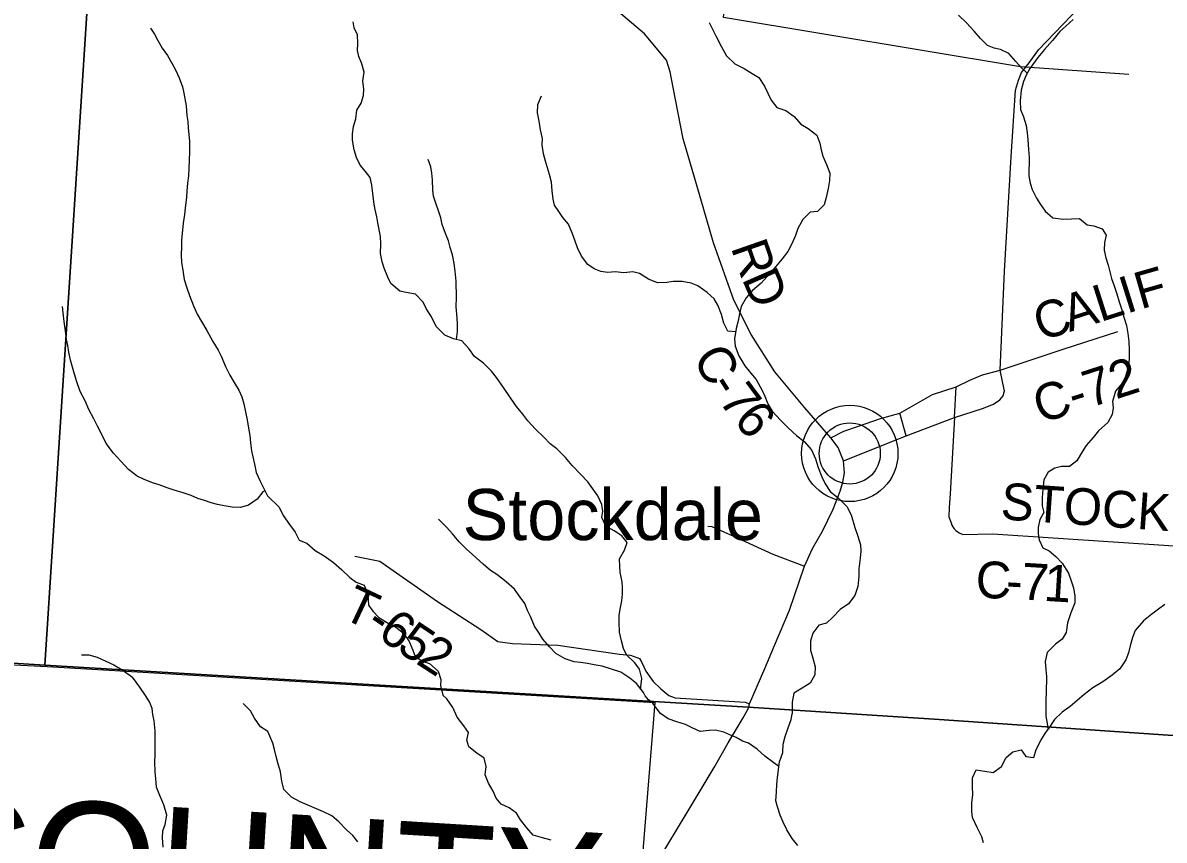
# Model space of a CAD drawing. Extents: x 0 to 40.8, y 0 to 22.
# Drawn here: x 3.414 to 5.177, y 17.063 to 18.326 of the extents above; entities that cross this region are included whole.
import ezdxf

# ---------------------------------------------------------------- set-up
doc = ezdxf.new("R2010")
doc.units = 0
for name, color, linetype in [('Default', 7, 'Continuous'), ('GM_X_County_Road', 7, 'Continuous'), ('GM_X_County_Road_Text', 7, 'Continuous'), ('GM_X_County_Text', 7, 'Continuous'), ('GM_X_Minor_River', 7, 'Continuous'), ('GM_X_Section', 7, 'Continuous'), ('GM_X_State_Route', 7, 'Continuous'), ('GM_X_Township_Road', 7, 'Continuous'), ('GM_X_Township_Road_Text', 7, 'Continuous'), ('GM_X_Unincorporated', 7, 'Continuous'), ('GM_X_Unincorporated_Location', 7, 'Continuous'), ('GM_X_Unincorporated_Text', 7, 'Continuous'), ('SH_Cut_Line', 7, 'Continuous')]:
    doc.layers.add(name, color=color, linetype=linetype)

msp = doc.modelspace()

# ---------------------------------------------------------------- linework, layer by layer
at = {"layer": 'Default'}
for points in [[(3.6829, 20.9), (2.1, 20.9), (2.1, 17.4153), (2.4594, 17.3966), (2.8463, 17.3693), (2.8484, 17.3691), (3.1244, 17.3534), (3.4481, 17.3334), (3.5638, 19.132), (3.5742, 19.2945), (3.575, 19.3064), (3.6386, 20.2396), (3.6672, 20.5588), (3.6703, 20.6733)], [(2.1, 16.4387), (2.1, 14.1), (8.9, 14.1), (8.9, 16.9831), (7.7161, 17.0658), (7.7144, 17.066), (7.54, 17.0745), (7.4495, 17.0841), (6.9172, 17.1197), (6.1785, 17.166), (5.6278, 17.197), (5.3407, 17.2146), (4.8294, 17.2493), (4.5348, 17.2687), (3.4481, 17.3334), (3.1244, 17.3534), (2.8484, 17.3691), (2.8463, 17.3693), (2.4594, 17.3966), (2.4379, 17.0913), (2.3911, 16.4258)]]:
    msp.add_lwpolyline(points, close=True, dxfattribs=at)
msp.add_lwpolyline([(7.7204, 20.9), (3.6829, 20.9), (3.6703, 20.6733), (3.6672, 20.5588), (3.6386, 20.2396), (3.575, 19.3064), (3.5742, 19.2945), (3.5638, 19.132), (3.4481, 17.3334), (4.5348, 17.2687), (4.8294, 17.2493), (5.3407, 17.2146), (5.6278, 17.197), (6.1785, 17.166), (6.9172, 17.1197)], dxfattribs=at)
at = {"layer": 'GM_X_County_Road'}
for points in [[(4.6816, 17.6488), (4.6733, 17.6695), (4.6618, 17.6847), (4.6216, 17.7308), (4.5756, 17.7865), (4.5388, 17.8444), (4.5119, 17.897), (4.4808, 17.9857), (4.4554, 18.0725), (4.4339, 18.1463), (4.4184, 18.2259), (4.4138, 18.2499), (4.4082, 18.2681), (4.374, 18.3086), (4.29, 18.3799)], [(4.9235, 17.789), (5.0206, 17.8217), (5.1052, 17.8487)], [(4.8531, 17.7162), (4.8463, 17.5982), (4.8448, 17.577), (4.8443, 17.5626), (4.8478, 17.5533), (4.8489, 17.5499), (4.8504, 17.5469), (4.8523, 17.5442), (4.855, 17.5415), (4.8599, 17.5377), (4.866, 17.535), (4.9121, 17.5364), (5.285, 17.5118), (5.4395, 17.4984), (5.6472, 17.4678), (5.8268, 17.441), (5.8904, 17.4325), (5.9002, 17.4317), (5.9067, 17.4313), (5.9128, 17.4316), (5.9208, 17.4358), (5.9239, 17.4468), (5.9261, 17.4652)]]:
    msp.add_lwpolyline(points, dxfattribs=at)
at = {"layer": 'GM_X_Minor_River'}
for points in [[(4.9651, 18.2477), (4.9564, 18.2559), (4.9478, 18.2659), (4.9369, 18.2781), (4.924, 18.2846), (4.9142, 18.2865), (4.904, 18.2908), (4.8931, 18.3014), (4.8833, 18.3129), (4.8713, 18.3255), (4.8589, 18.3373)], [(3.6112, 18.3175), (3.6171, 18.3079), (3.6226, 18.2983), (3.6292, 18.2864), (3.6373, 18.2753), (3.6439, 18.263), (3.6498, 18.253), (3.6552, 18.2408), (3.6603, 18.2266), (3.6627, 18.2171), (3.6661, 18.1973), (3.6674, 18.1825), (3.6687, 18.1729), (3.6693, 18.1627), (3.6702, 18.1532), (3.6711, 18.1421), (3.6712, 18.127), (3.6706, 18.1133), (3.6703, 18.1008), (3.6697, 18.0894), (3.6684, 18.0781), (3.667, 18.0663), (3.6665, 18.0565), (3.6646, 18.0394), (3.6637, 18.0296), (3.6615, 18.0163), (3.6591, 17.9898), (3.6589, 17.9803), (3.6587, 17.9674), (3.6592, 17.9553), (3.6609, 17.9435), (3.6632, 17.929), (3.6672, 17.916), (3.6711, 17.9045), (3.6776, 17.8885), (3.6834, 17.8755), (3.69, 17.8643), (3.6981, 17.8505), (3.7073, 17.8332), (3.7154, 17.8202), (3.7201, 17.8106), (3.727, 17.7949), (3.7336, 17.7811), (3.7402, 17.77), (3.7475, 17.7581), (3.7523, 17.7477), (3.7551, 17.737), (3.7582, 17.7222), (3.7603, 17.7126), (3.7627, 17.6997), (3.7644, 17.6879), (3.7657, 17.6769), (3.767, 17.6647), (3.769, 17.6552), (3.7715, 17.6437), (3.7743, 17.6311), (3.7805, 17.6177), (3.7856, 17.6074), (3.7918, 17.5947)], [(4.3686, 17.2962), (4.3685, 17.3001), (4.3698, 17.313), (4.3664, 17.327), (4.3593, 17.3369), (4.3465, 17.3495), (4.3416, 17.359), (4.3383, 17.3712), (4.3357, 17.3845), (4.3351, 17.3996), (4.3351, 17.4102), (4.3367, 17.4201), (4.3391, 17.4326), (4.3399, 17.4432), (4.3403, 17.4527), (4.3396, 17.4622), (4.3367, 17.4766), (4.336, 17.4861), (4.3357, 17.4974), (4.343, 17.5111), (4.3472, 17.5228), (4.3389, 17.5334), (4.3273, 17.5407), (4.3144, 17.548), (4.3081, 17.5613), (4.3097, 17.5715), (4.3082, 17.5818), (4.3018, 17.5951), (4.2868, 17.6164), (4.2752, 17.6286), (4.2624, 17.642), (4.2519, 17.6542), (4.2387, 17.6675), (4.2285, 17.6752), (4.2187, 17.6855), (4.2059, 17.6981), (4.1939, 17.711), (4.1864, 17.7209), (4.1763, 17.7327), (4.1669, 17.7464), (4.1564, 17.7621), (4.1455, 17.7777), (4.138, 17.7876), (4.1252, 17.7998), (4.1116, 17.8101), (4.1026, 17.8227), (4.0921, 17.8345), (4.0792, 17.8376), (4.0656, 17.843), (4.0525, 17.8567), (4.045, 17.8716), (4.0367, 17.8845), (4.0323, 17.894), (4.0202, 17.9066), (4.0062, 17.9089), (3.996, 17.9113), (3.9825, 17.9227), (3.9776, 17.9326), (3.972, 17.9467), (3.9687, 17.9566), (3.9661, 17.9695), (3.9669, 17.9843), (3.9662, 17.9956), (3.9622, 18.0165), (3.9608, 18.026), (3.9578, 18.0393), (3.956, 18.0492), (3.9531, 18.075), (3.9502, 18.0864), (3.9434, 18.0959), (3.9351, 18.1058), (3.9295, 18.1176), (3.9254, 18.1294), (3.9233, 18.1442), (3.9233, 18.154), (3.9245, 18.1654), (3.928, 18.1771), (3.9296, 18.1908), (3.9365, 18.2017), (3.9403, 18.2135), (3.9404, 18.223), (3.939, 18.2359), (3.9409, 18.2491), (3.9376, 18.262), (3.9328, 18.2734), (3.9306, 18.2829), (3.9314, 18.2935), (3.9307, 18.3068), (3.9255, 18.3178), (3.924, 18.3273)], [(4.4741, 18.3263), (4.4794, 18.3145), (4.4846, 18.3043), (4.4928, 18.2887), (4.5007, 18.2746), (4.5135, 18.262), (4.5282, 18.2551), (4.5406, 18.2474), (4.5505, 18.2413), (4.5595, 18.2276), (4.5699, 18.2063), (4.5786, 18.1949), (4.5922, 18.1902), (4.6054, 18.1807), (4.6155, 18.1689), (4.6268, 18.1623), (4.6404, 18.152), (4.6449, 18.1399), (4.6467, 18.1296), (4.6493, 18.1197), (4.6552, 18.1068), (4.6601, 18.0935), (4.6596, 18.0821), (4.658, 18.0696), (4.6545, 18.056), (4.6518, 18.0443), (4.6415, 18.0341), (4.6298, 18.033), (4.6187, 18.0217), (4.6107, 18.0077), (4.6072, 17.9971), (4.6019, 17.985), (4.5957, 17.9725), (4.5869, 17.9612), (4.5766, 17.9488), (4.5679, 17.9386), (4.5542, 17.9235), (4.5408, 17.9122), (4.5313, 17.9009), (4.5236, 17.8873), (4.5209, 17.8763), (4.5182, 17.8634), (4.5155, 17.8532), (4.5131, 17.8373), (4.5142, 17.8259), (4.5198, 17.8111), (4.5291, 17.7955), (4.5378, 17.7852), (4.5464, 17.7749), (4.5528, 17.7635), (4.5588, 17.7513), (4.5647, 17.7369), (4.5715, 17.7255), (4.5843, 17.7117), (4.5959, 17.6999), (4.6091, 17.6881), (4.6208, 17.6789), (4.6321, 17.6659), (4.638, 17.6523), (4.6421, 17.6386), (4.6481, 17.6245), (4.6529, 17.6135), (4.6608, 17.6017), (4.6732, 17.5917), (4.6868, 17.5784), (4.6935, 17.5658), (4.6987, 17.5461), (4.7035, 17.5328), (4.7076, 17.5195), (4.7083, 17.5093), (4.7071, 17.4986), (4.7051, 17.4824), (4.705, 17.4702), (4.7034, 17.4551)], [(5.036, 18.3306), (5.025, 18.3204), (5.0154, 18.3121), (5.0044, 18.2981), (4.9918, 18.2842), (4.9815, 18.2721), (4.9693, 18.2551), (4.9635, 18.2449), (4.9597, 18.2351), (4.9558, 18.2218), (4.9542, 18.2051), (4.9549, 18.1919), (4.9597, 18.1805), (4.9638, 18.1668), (4.9652, 18.1558), (4.9659, 18.1455), (4.9674, 18.13), (4.968, 18.1175), (4.9679, 18.0894), (4.9697, 18.078), (4.973, 18.0681), (4.9794, 18.0548), (4.9858, 18.0449), (4.9929, 18.0346), (5.0049, 18.0243), (5.0205, 18.0223), (5.0337, 18.0226), (5.0462, 18.0233), (5.0579, 18.0138), (5.0681, 18.0118), (5.0809, 18.0076), (5.0869, 17.9977), (5.0846, 17.9863), (5.0838, 17.9742), (5.0867, 17.9624), (5.09, 17.9514), (5.0926, 17.9411), (5.0956, 17.9309), (5.0997, 17.9191), (5.1034, 17.907), (5.1071, 17.8944), (5.1112, 17.8823), (5.1145, 17.8709), (5.1186, 17.8579), (5.1208, 17.8458), (5.1223, 17.8333), (5.1229, 17.8204), (5.1228, 17.8056), (5.1209, 17.7935), (5.117, 17.7795), (5.1116, 17.7689), (5.1017, 17.7564), (5.0971, 17.7409), (5.0978, 17.7307), (5.0966, 17.7208), (5.0897, 17.708), (5.0752, 17.6955), (5.0668, 17.6853)], [(4.5147, 17.8481), (4.5026, 17.8495), (4.4966, 17.8617), (4.4929, 17.8753), (4.4873, 17.8894), (4.4817, 17.8993), (4.4708, 17.9088), (4.4564, 17.9192), (4.4462, 17.9234), (4.4323, 17.9261), (4.4182, 17.9258), (4.4084, 17.9247), (4.394, 17.9241), (4.3804, 17.9295), (4.3665, 17.9383), (4.3559, 17.941), (4.3422, 17.9396), (4.3286, 17.9408), (4.3176, 17.9401), (4.3067, 17.9413), (4.2961, 17.9455), (4.2863, 17.9524), (4.2769, 17.9653), (4.2705, 17.9779), (4.2668, 17.9885), (4.2631, 17.9996), (4.2568, 18.0148), (4.2481, 18.0247), (4.2417, 18.0342), (4.235, 18.0437), (4.2328, 18.0532), (4.2317, 18.0661), (4.2303, 18.0794), (4.2273, 18.0915), (4.2244, 18.1014), (4.2214, 18.1121), (4.2181, 18.1231), (4.2159, 18.1371), (4.2163, 18.147), (4.2137, 18.1603), (4.2116, 18.1736), (4.209, 18.1865), (4.2094, 18.1993), (4.2152, 18.2126)], [(4.0835, 17.8366), (4.085, 17.8486), (4.0851, 17.8618), (4.0844, 17.8755), (4.0833, 17.8869), (4.0838, 17.9013), (4.0832, 17.9263), (4.0814, 17.9419), (4.0799, 17.9536), (4.0774, 17.9673), (4.074, 17.9787), (4.0715, 17.9889), (4.0666, 18), (4.0614, 18.014), (4.0596, 18.0243), (4.0566, 18.0338), (4.0518, 18.0471), (4.0484, 18.0577), (4.047, 18.0672), (4.0467, 18.0828), (4.0456, 18.0934), (4.0442, 18.1029), (4.0401, 18.1147)], [(3.7878, 17.6028), (3.7847, 17.601), (3.7757, 17.5897), (3.7627, 17.5805), (3.7501, 17.577), (3.7372, 17.5776), (3.7251, 17.5794), (3.7145, 17.5815), (3.7047, 17.5839), (3.6946, 17.5876), (3.684, 17.5908), (3.6739, 17.5956), (3.6614, 17.5996), (3.6475, 17.6037), (3.6366, 17.6073), (3.6245, 17.6117), (3.614, 17.6149), (3.6004, 17.6205), (3.5906, 17.6253), (3.5772, 17.6354), (3.5653, 17.6486), (3.5538, 17.6609), (3.5427, 17.6756), (3.5358, 17.6897), (3.5292, 17.7028), (3.5237, 17.7139), (3.516, 17.7281), (3.5102, 17.7419), (3.5026, 17.7561), (3.4972, 17.771), (3.4936, 17.7828), (3.4904, 17.7939), (3.4876, 17.8046), (3.4852, 17.8171), (3.4834, 17.827), (3.4814, 17.8366), (3.4797, 17.8499), (3.4777, 17.8643), (3.4761, 17.8777), (3.4751, 17.8875)], [(5.0668, 17.6853), (5.0561, 17.6725), (5.05, 17.6627), (5.0416, 17.6491), (5.0306, 17.6404), (5.0184, 17.6401), (5.0078, 17.6379), (4.9976, 17.6315), (4.9907, 17.6198), (4.9891, 17.6047), (4.9882, 17.5925), (4.9882, 17.5796), (4.9907, 17.5694), (4.9846, 17.5584), (4.9819, 17.5463), (4.9822, 17.5368), (4.9837, 17.527), (4.9893, 17.5148), (4.9991, 17.5102), (5.0096, 17.501), (5.019, 17.4907), (5.0292, 17.4755), (5.0332, 17.4637), (5.0366, 17.4527), (5.0388, 17.4398), (5.0387, 17.4299), (5.0326, 17.4141), (5.0272, 17.3989), (5.0252, 17.3841), (5.0191, 17.3736), (5.0088, 17.3657), (4.9958, 17.3528), (4.9927, 17.3392), (4.9942, 17.3263), (4.9948, 17.3161), (4.9947, 17.2907), (4.9942, 17.2801), (4.9941, 17.2547), (4.9975, 17.2347)], [(3.7918, 17.5947), (3.8099, 17.5776), (3.8159, 17.5646), (3.8257, 17.5505), (3.8347, 17.5387), (3.8407, 17.5266), (3.8527, 17.5216), (3.8655, 17.5105), (3.8791, 17.5024), (3.8938, 17.4921), (3.9066, 17.4807), (3.9187, 17.4688), (3.9285, 17.4616), (3.9409, 17.457), (3.9469, 17.4425), (3.9476, 17.4262), (3.9543, 17.4167), (3.9637, 17.4071), (3.9784, 17.3983), (3.9901, 17.3922), (4.0018, 17.383), (4.0108, 17.3701), (4.0164, 17.3564), (4.0198, 17.3469), (4.0322, 17.3392), (4.042, 17.3358), (4.0552, 17.3243), (4.0597, 17.3114), (4.0589, 17.3019), (4.0628, 17.2872)], [(4.3905, 17.2695), (4.3869, 17.2749), (4.3805, 17.2801), (4.375, 17.2861), (4.3726, 17.291), (4.3618, 17.3051), (4.3516, 17.3131), (4.3373, 17.3226), (4.3229, 17.3273), (4.3089, 17.3319), (4.2964, 17.3339), (4.2862, 17.3362), (4.2753, 17.3374), (4.2654, 17.3386), (4.2514, 17.3432), (4.2371, 17.3513), (4.2273, 17.3616), (4.2172, 17.3734), (4.2112, 17.3829), (4.2044, 17.3936), (4.1981, 17.4084), (4.1936, 17.4179), (4.1891, 17.4286), (4.182, 17.4385), (4.1734, 17.4506), (4.1606, 17.4621), (4.1462, 17.4736), (4.1364, 17.4797), (4.1251, 17.4892), (4.1086, 17.5041), (4.0984, 17.5129), (4.0879, 17.524), (4.0777, 17.5365), (4.0687, 17.5461), (4.0559, 17.559)], [(4.7034, 17.4551), (4.6988, 17.4411), (4.6893, 17.4282), (4.6763, 17.4192), (4.6649, 17.4075), (4.655, 17.3981), (4.6432, 17.3951), (4.6341, 17.3827), (4.6306, 17.3706), (4.6305, 17.3565), (4.6342, 17.344), (4.6375, 17.3307), (4.6371, 17.3186), (4.6302, 17.3057), (4.6176, 17.2978), (4.6047, 17.2903), (4.602, 17.2763), (4.602, 17.2581)], [(5.178, 17.4272), (5.1681, 17.4197), (5.1575, 17.4122), (5.1446, 17.402), (5.132, 17.3869), (5.1277, 17.3763), (5.1242, 17.3631), (5.1215, 17.3525), (5.1177, 17.3415), (5.1081, 17.3279), (5.0963, 17.3177), (5.0819, 17.3076), (5.0667, 17.2982), (5.053, 17.2881), (5.0423, 17.279), (5.0313, 17.2696), (5.0191, 17.2606), (5.0073, 17.2496), (4.9975, 17.2347)], [(3.5046, 17.3492), (3.5159, 17.3493), (3.5288, 17.3457), (3.5423, 17.3397), (3.5547, 17.3338), (3.5674, 17.3263), (3.5832, 17.3151)], [(3.6306, 17.0522), (3.6298, 17.0674), (3.6303, 17.0776), (3.6337, 17.0871), (3.6364, 17.1019), (3.6319, 17.1179), (3.6255, 17.1323), (3.6206, 17.1452), (3.6191, 17.1581), (3.6184, 17.168), (3.6177, 17.1847), (3.6181, 17.1942), (3.6181, 17.2044), (3.6185, 17.2189), (3.6182, 17.2321), (3.6167, 17.2473), (3.6149, 17.2572), (3.6134, 17.2667), (3.6096, 17.2766), (3.6036, 17.2865), (3.5945, 17.2994), (3.5832, 17.3151)], [(4.23, 17.0629), (4.2164, 17.0667), (4.202, 17.0708), (4.1925, 17.0822), (4.1827, 17.0944), (4.1766, 17.1046), (4.1652, 17.113), (4.1527, 17.1187), (4.1448, 17.1281), (4.1402, 17.1388), (4.133, 17.1509), (4.1281, 17.1638), (4.1293, 17.1767), (4.1266, 17.1896), (4.1149, 17.1976), (4.1027, 17.2074), (4.0997, 17.2177), (4.102, 17.2294), (4.0952, 17.2397), (4.0849, 17.2533), (4.0781, 17.2681), (4.0686, 17.2812), (4.0628, 17.2872)], [(3.7921, 17.2312), (3.7809, 17.2384), (3.7719, 17.2513), (3.7654, 17.2627), (3.7541, 17.2742)], [(4.5817, 17.1769), (4.5737, 17.1823), (4.56, 17.1926), (4.5483, 17.2036), (4.5347, 17.2127), (4.5252, 17.2161), (4.5157, 17.2218), (4.5059, 17.226), (4.4964, 17.2301), (4.4835, 17.2328), (4.4737, 17.2324), (4.46, 17.2309), (4.4479, 17.2366), (4.4373, 17.2415), (4.424, 17.2457), (4.4104, 17.2503), (4.399, 17.2586), (4.3905, 17.2695)], [(4.6108, 17.0549), (4.6024, 17.0659), (4.5941, 17.0791), (4.5884, 17.0909), (4.5835, 17.1015), (4.5793, 17.1144), (4.5767, 17.1239), (4.5778, 17.1372), (4.5786, 17.1497), (4.5797, 17.1596), (4.5812, 17.1725), (4.5824, 17.1842), (4.5877, 17.1983), (4.5881, 17.2112), (4.5911, 17.2233), (4.596, 17.2366), (4.6006, 17.2495), (4.602, 17.2581)], [(3.8053, 17.1923), (3.8027, 17.2033), (3.8, 17.2128), (3.7921, 17.2312)], [(4.8976, 17.059), (4.8953, 17.0685), (4.8877, 17.0825), (4.8809, 17.0981), (4.8798, 17.1076), (4.8798, 17.1208), (4.8813, 17.1337), (4.8809, 17.1455), (4.8809, 17.1592), (4.8866, 17.1717), (4.8995, 17.1698), (4.9128, 17.1675), (4.9256, 17.177), (4.9325, 17.1906), (4.9431, 17.1994), (4.9556, 17.2024), (4.9628, 17.1922), (4.9753, 17.1906), (4.9791, 17.2032), (4.9863, 17.2168), (4.9919, 17.2263), (4.9975, 17.2347)], [(3.9311, 17.0603), (3.9235, 17.0701), (3.914, 17.0788), (3.9019, 17.0914), (3.8909, 17.1005), (3.8784, 17.1069), (3.864, 17.113), (3.8531, 17.1179), (3.8421, 17.1225), (3.8288, 17.1293), (3.8171, 17.1415), (3.8137, 17.154), (3.8118, 17.1684), (3.808, 17.1828), (3.8053, 17.1923)]]:
    msp.add_lwpolyline(points, dxfattribs=at)
at = {"layer": 'GM_X_Section'}
for points in [[(5.1222, 18.2458), (4.9546, 18.2574), (4.4961, 18.3336), (4.6019, 19.2378), (5.5995, 19.1863), (5.5864, 18.978)], [(3.2542, 16.2539), (3.3398, 17.3372), (3.4517, 17.3312), (4.3898, 17.2759), (4.2989, 16.1489), (3.9097, 16.1796)]]:
    msp.add_lwpolyline(points, dxfattribs=at)
at = {"layer": 'GM_X_State_Route'}
for points in [[(4.535, 17.2682), (4.5362, 17.2738), (4.5601, 17.3282), (4.5751, 17.3638), (4.598, 17.4186), (4.6211, 17.4865), (4.6336, 17.5137), (4.6489, 17.5406), (4.6655, 17.5743), (4.6763, 17.602), (4.6802, 17.616), (4.683, 17.6304), (4.6816, 17.6488), (4.7781, 17.6875), (4.8531, 17.7162), (4.8553, 17.7633), (4.8767, 17.7738), (4.8961, 17.7816), (4.9235, 17.789), (4.9303, 17.9421), (4.9406, 18.1188), (4.947, 18.2214), (4.9516, 18.237), (4.9563, 18.2487), (4.9682, 18.2638), (4.9824, 18.2839), (5.0708, 18.3759)], [(4.3372, 16.7202), (4.3393, 16.7224), (4.342, 16.7268), (4.3441, 16.7314), (4.3455, 16.74), (4.3539, 16.8267), (4.3577, 16.8686), (4.3632, 16.9206), (4.3648, 16.9424), (4.3665, 16.9606), (4.3683, 16.9753), (4.3711, 16.987), (4.3745, 16.9957), (4.3786, 17.0031), (4.3919, 17.0267), (4.4431, 17.1112), (4.4815, 17.1754), (4.5035, 17.2134), (4.5266, 17.2521), (4.535, 17.2682)]]:
    msp.add_lwpolyline(points, dxfattribs=at)
at = {"layer": 'GM_X_Township_Road'}
msp.add_line((4.7781, 17.6875), (4.7685, 17.7224), dxfattribs=at)
for points in [[(4.8531, 17.7162), (4.896, 17.7301), (4.9131, 17.7368), (4.9227, 17.7433), (4.928, 17.7494), (4.9303, 17.7573), (4.9276, 17.7691), (4.9235, 17.789)], [(4.6618, 17.6847), (4.6817, 17.6949), (4.7045, 17.7025), (4.7384, 17.7145), (4.7685, 17.7224), (4.8188, 17.7516), (4.8553, 17.7633)], [(4.4717, 17.548), (4.4782, 17.5476), (4.5117, 17.5326), (4.5419, 17.5189)], [(4.5419, 17.5189), (4.5722, 17.5051), (4.6211, 17.4865)], [(3.9267, 17.5016), (3.9653, 17.494), (4.0544, 17.4318), (4.1215, 17.3887), (4.1478, 17.37), (4.1702, 17.3671), (4.2402, 17.3643), (4.3354, 17.3503), (4.3527, 17.3489), (4.3665, 17.3438), (4.3701, 17.3373), (4.3762, 17.3243), (4.3874, 17.3084), (4.3993, 17.2969), (4.4116, 17.2868), (4.4216, 17.2832), (4.5296, 17.2762), (4.5362, 17.2738)]]:
    msp.add_lwpolyline(points, dxfattribs=at)
at = {"layer": 'GM_X_Unincorporated'}
for radius in [0.0744, 0.0472]:
    msp.add_circle((4.6911, 17.6604), radius, dxfattribs=at)
at = {"layer": 'GM_X_Unincorporated_Location'}
msp.add_line((4.6911, 17.6604), (4.6911, 17.6604), dxfattribs=at)
at = {"layer": 'SH_Cut_Line'}
for points in [[(7.7204, 20.9), (2.1, 20.9), (2.1, 17.4153), (2.4594, 17.3966), (2.8463, 17.3693), (2.8484, 17.3691), (3.1244, 17.3534), (3.4481, 17.3334), (4.5348, 17.2687), (4.8294, 17.2493), (5.3407, 17.2146), (5.6278, 17.197), (6.1785, 17.166), (6.9172, 17.1197), (7.4495, 17.0841), (7.4798, 17.5479), (7.4963, 17.9476), (7.5246, 18.2047), (7.5789, 18.8336), (7.595, 19.0259), (7.6007, 19.1025), (7.6007, 19.1071), (7.6192, 19.376), (7.7055, 20.511)], [(2.1, 17.4153), (2.1, 14.1), (8.9, 14.1), (8.9, 16.9831), (7.7161, 17.0658), (7.7144, 17.066), (7.54, 17.0745), (7.4495, 17.0841), (6.9172, 17.1197), (6.1785, 17.166), (5.6278, 17.197), (5.3407, 17.2146), (4.8294, 17.2493), (4.5348, 17.2687), (3.4481, 17.3334), (3.1244, 17.3534), (2.8484, 17.3691), (2.8463, 17.3693), (2.4594, 17.3966)]]:
    msp.add_lwpolyline(points, close=True, dxfattribs=at)

# ---------------------------------------------------------------- texts
at = {"layer": 'GM_X_County_Road_Text'}
for s, height, rotation, p in [('R', 0.0568, 289.2015, (4.5069, 17.9789)), ('D', 0.0568, 293.5356, (4.5239, 17.9305)), ('F', 0.0568, 15.9774, (5.1404, 17.8829)), ('I', 0.0568, 17.4425, (5.1185, 17.876)), ('A', 0.0568, 17.7334, (5.0304, 17.8478)), ('L', 0.0568, 17.7288, (5.0781, 17.8631)), ('C', 0.0568, 17.7363, (4.986, 17.8336)), ('C', 0.0568, 300.7877, (4.4472, 17.8073)), ('C-72', 0.05682, 17.8979, (4.9857, 17.7062)), ('-', 0.0568, 302.7988, (4.4722, 17.7654)), ('7', 0.0568, 306.6155, (4.4872, 17.7424)), ('6', 0.0568, 309.7263, (4.5101, 17.7116)), ('STOCKDALE', 0.05682, 355.9547, (4.9231, 17.5589)), ('C', 0.0568, 358.915, (4.8853, 17.4371)), ('7', 0.0568, 356.5684, (4.9547, 17.435)), ('1', 0.0568, 356.4594, (4.9896, 17.4329)), ('-', 0.0568, 356.9622, (4.9315, 17.4363))]:
    msp.add_text(s, height=height, rotation=rotation, dxfattribs=at).set_placement(p)
at = {"layer": 'GM_X_County_Text'}
msp.add_text('SCIOTO COUNTY', height=0.189394, rotation=356.5147, dxfattribs=at).set_placement((2.1971, 17.0129))
at = {"layer": 'GM_X_Township_Road_Text'}
for s, rotation, p in [('T', 334.8226, (3.9042, 17.4075)), ('6', 325.1725, (3.9596, 17.3774)), ('-', 325.2382, (3.9405, 17.3907)), ('5', 326.3845, (3.9894, 17.3567)), ('2', 327.145, (4.0193, 17.3369))]:
    msp.add_text(s, height=0.0568, rotation=rotation, dxfattribs=at).set_placement(p)
at = {"layer": 'GM_X_Unincorporated_Text'}
msp.add_text('Stockdale', height=0.07898, rotation=0, dxfattribs=at).set_placement((4.0932, 17.5266))

doc.saveas('drawing.dxf')
